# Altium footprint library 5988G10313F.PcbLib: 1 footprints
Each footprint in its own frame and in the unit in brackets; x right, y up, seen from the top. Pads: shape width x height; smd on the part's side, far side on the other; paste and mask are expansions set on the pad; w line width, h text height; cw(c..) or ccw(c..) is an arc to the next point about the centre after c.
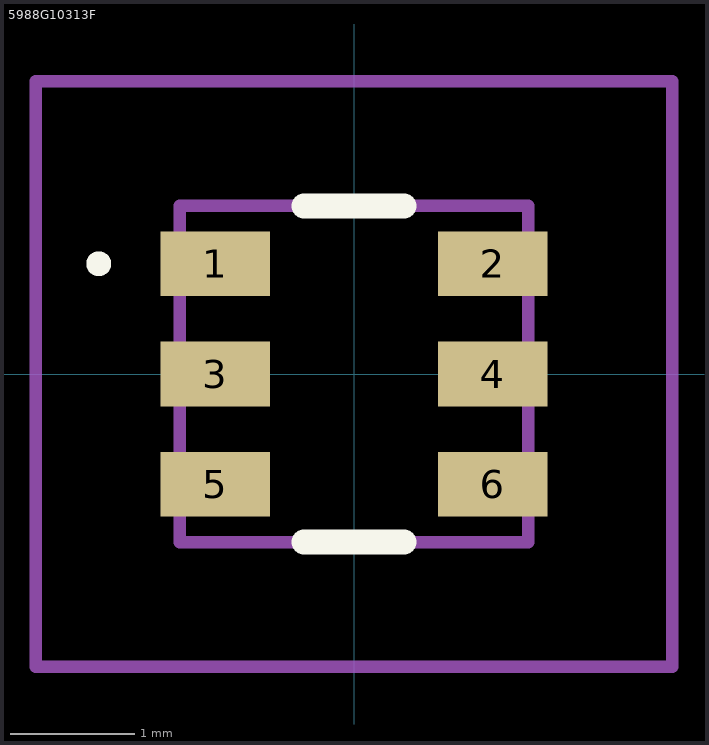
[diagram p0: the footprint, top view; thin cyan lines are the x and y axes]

## 5988G10313F [mm]
pads (6):
  rect 0.88x0.52 smd: 1(-1.115,0.885) 2(1.115,0.885) 3(-1.115,0) 4(1.115,0) 5(-1.115,-0.885) 6(1.115,-0.885)
Top Overlay:
  lines w0.1: -2.1,0.885 cw(c-2.05,0.885) -2,0.885 ; -2.1,0.885 -2.1,0.885 ; -2.1,0.885 ccw(c-2.05,0.885) -2,0.885 ; -2,0.885 -2,0.885
  lines w0.2: -0.4,-1.35 0.4,-1.35 ; -0.4,1.35 0.4,1.35
Mechanical 15:
  lines w0.1: -1.4,-1.35 1.4,-1.35 1.4,1.35 -1.4,1.35 -1.4,-1.35
Mechanical 20:
  lines w0.1: -2.555,-2.35 2.555,-2.35 2.555,2.35 -2.555,2.35 -2.555,-2.35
